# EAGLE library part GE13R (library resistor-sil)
SIL RESISTOR
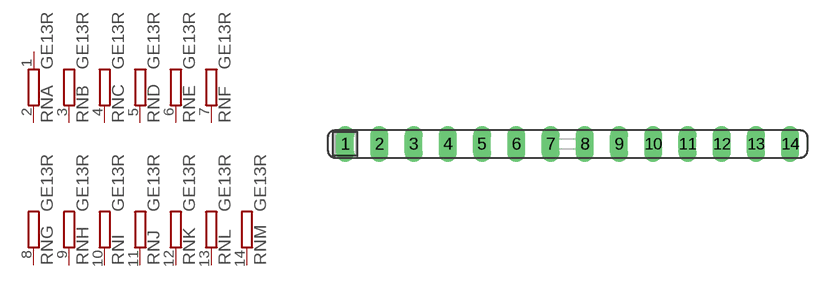
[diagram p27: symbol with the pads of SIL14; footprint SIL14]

Designator prefix RN; gates A=R-NV B=R-NV1 C=R-NV1 D=R-NV1 E=R-NV1 F=R-NV1 G=R-NV1 H=R-NV1 I=R-NV1 J=R-NV1 K=R-NV1 L=R-NV1 M=R-NV1

## GE13R (OC_FARNELL: unknown; OC_NEWARK: unknown)  [SIL14]
1  A:1  pas
2  A:2  pas
3  B:2  pas
4  C:2  pas
5  D:2  pas
6  E:2  pas
7  F:2  pas
8  G:2  pas
9  H:2  pas
10  I:2  pas
11  J:2  pas
12  K:2  pas
13  L:2  pas
14  M:2  pas

## Footprint SIL14 (pad centres in mm)
Single In Line
drill 0.813 long: 1 -16.51,0; 2 -13.97,0; 3 -11.43,0; 4 -8.89,0; 5 -6.35,0; 6 -3.81,0; 7 -1.27,0; 8 1.27,0; 9 3.81,0; 10 6.35,0; 11 8.89,0; 12 11.43,0; 13 13.97,0; 14 16.51,0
